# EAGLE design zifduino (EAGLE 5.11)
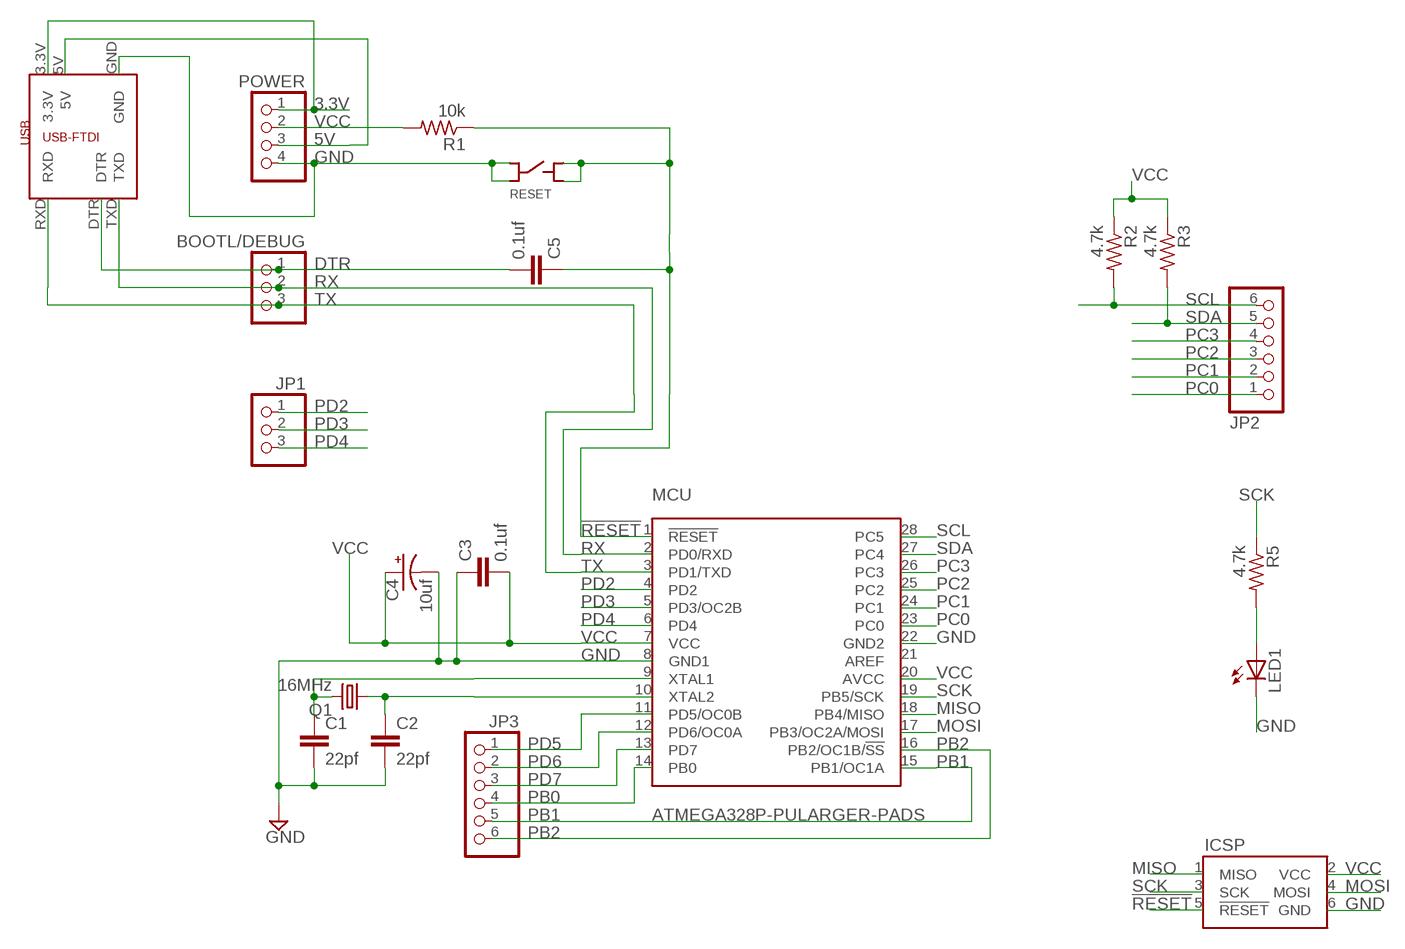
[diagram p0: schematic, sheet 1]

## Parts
BOOTL/DEBUG  PINHD-1X3  [1X03]
C1  22pf  C-EUC0805  [C0805]
C2  22pf  C-EUC0805  [C0805]
C3  0.1uf  C-EUC0805  [C0805]
C4  10uf  CPOL-USE2-4  [E2-4]
C5  0.1uf  C-EUC0805  [C0805]
ICSP  HEADER-AVR-PROG  [HEADER-AVR-PROG]
JP1  PINHD-1X3  [1X03]
JP2  PINHD-1X6  [1X06]
JP3  PINHD-1X6  [1X06]
LED1  LED5MM  [LED5MM]
MCU  ATMEGA328P-PULARGER-PADS  [DIL28-3-LARGER-PADS]
POWER  PINHD-1X4  [1X04]
Q1  16MHz  CRYSTALHC49U-V  [HC49U-V]
R1  10k  R-US_R0805  [R0805]
R2  4.7k  R-US_R1206  [R1206]
R3  4.7k  R-US_R1206  [R1206]
R5  4.7k  R-US_R1206  [R1206]
RESET  SFE-PUSHBUTTON-SWITCH  [SFE-PUSHBUTTON-SWITCH]
USB-FTDI  SFE-FTDI-BREAKOUT-MIN  [SFE-FTDI-BREAKOUT-MIN]

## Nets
3.3V: POWER.1 USB-FTDI.3.3V
5V: POWER.3 USB-FTDI.5V
!RESET: C5.1 ICSP.5(!RESET) MCU.1(!RESET) R1.1 RESET.O@1(O) RESET.O@2(O)
DTR: BOOTL/DEBUG.1 C5.2 USB-FTDI.DTR
GND: C1.2 C2.2 C3.1 C4.- ICSP.6(GND) LED1.K(C) MCU.8(GND1) MCU.22(GND2) POWER.4 RESET.C@1(C) RESET.C@2(C) USB-FTDI.GND
MISO: ICSP.1(MISO) MCU.18(PB4/MISO)
MOSI: ICSP.4(MOSI) MCU.17(PB3/OC2A/MOSI)
N$2: C2.1 MCU.10(XTAL2) Q1.1
N$3: C1.1 MCU.9(XTAL1) Q1.2
N$4: LED1.A R5.2
PB0: JP3.4 MCU.14(PB0)
PB1: JP3.5 MCU.15(PB1/OC1A)
PB2: JP3.6 MCU.16(PB2/OC1B/!SS)
PC0: JP2.1 MCU.23(PC0)
PC1: JP2.2 MCU.24(PC1)
PC2: JP2.3 MCU.25(PC2)
PC3: JP2.4 MCU.26(PC3)
PD2: JP1.1 MCU.4(PD2)
PD3: JP1.2 MCU.5(PD3/OC2B)
PD4: JP1.3 MCU.6(PD4)
PD5: JP3.1 MCU.11(PD5/OC0B)
PD6: JP3.2 MCU.12(PD6/OC0A)
PD7: JP3.3 MCU.13(PD7)
RX: BOOTL/DEBUG.2 MCU.2(PD0/RXD) USB-FTDI.TXD
SCK: ICSP.3(SCK) MCU.19(PB5/SCK) R5.1
SCL: JP2.6 MCU.28(PC5) R2.2
SDA: JP2.5 MCU.27(PC4) R3.2
TX: BOOTL/DEBUG.3 MCU.3(PD1/TXD) USB-FTDI.RXD
VCC: C3.2 C4.+ ICSP.2(VCC) MCU.7(VCC) MCU.20(AVCC) POWER.2 R1.2 R2.1 R3.1
Unconnected: MCU.21(AREF)

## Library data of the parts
BOOTL/DEBUG JP1 = pinhead:PINHD-1X3: PIN HEADER
C1-C3 C5 = rcl:C-EU: CAPACITOR, European symbol
C4 = rcl:CPOL-US: POLARIZED CAPACITOR, American symbol
ICSP = trl:HEADER-AVR-PROG
JP2 JP3 = pinhead:PINHD-1X6: PIN HEADER
LED1 = led:LED: LED
MCU = trl:ATMEGA328P-PU
POWER = pinhead:PINHD-1X4: PIN HEADER
Q1 = crystal:CRYSTAL: CRYSTAL; OC_FARNELL: 1666969; OC_NEWARK: unknown
R1-R3 R5 = resistor:R-US_: RESISTOR, American symbol
RESET = trl:SFE-PUSHBUTTON-SWITCH
USB-FTDI = trl:SFE-FTDI-BREAKOUT-MIN

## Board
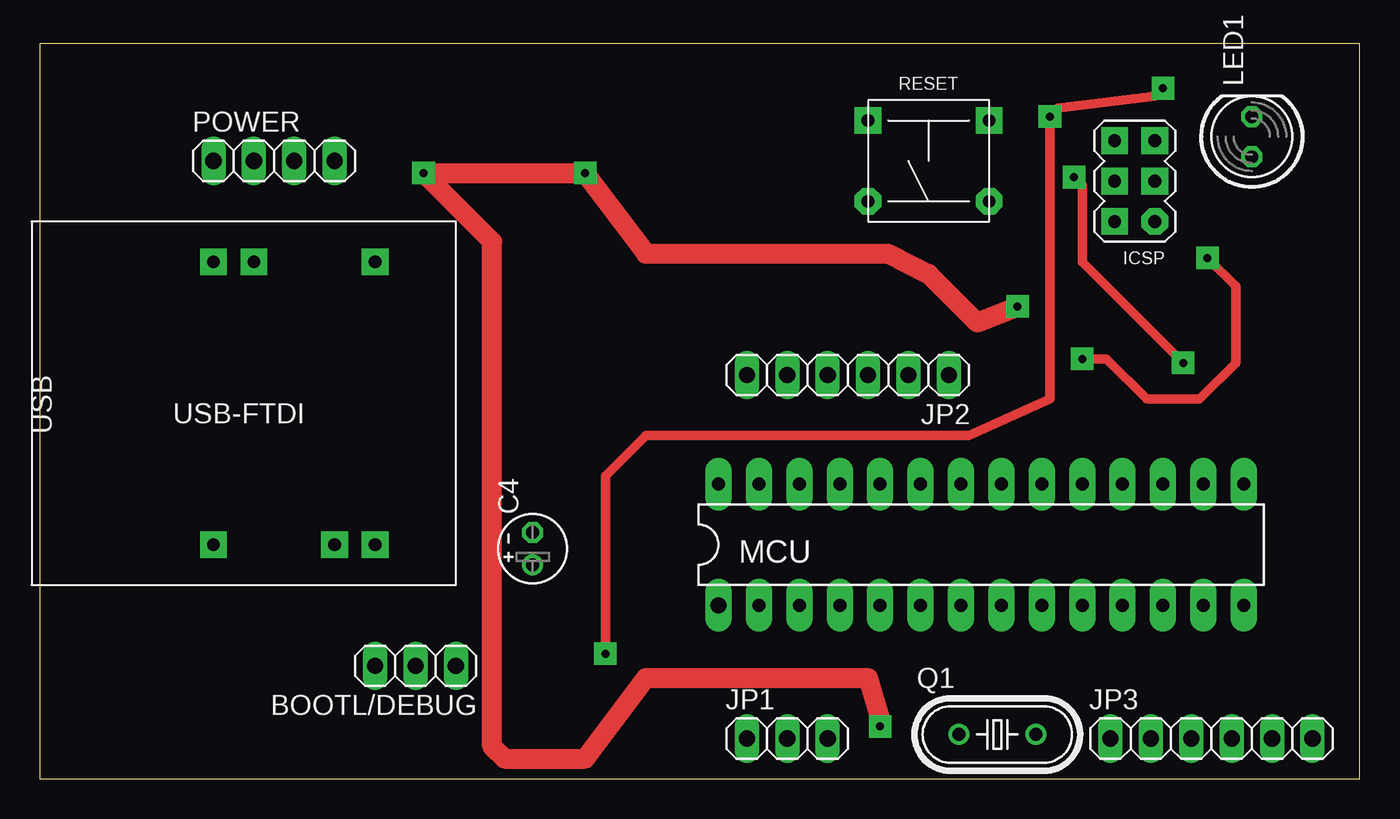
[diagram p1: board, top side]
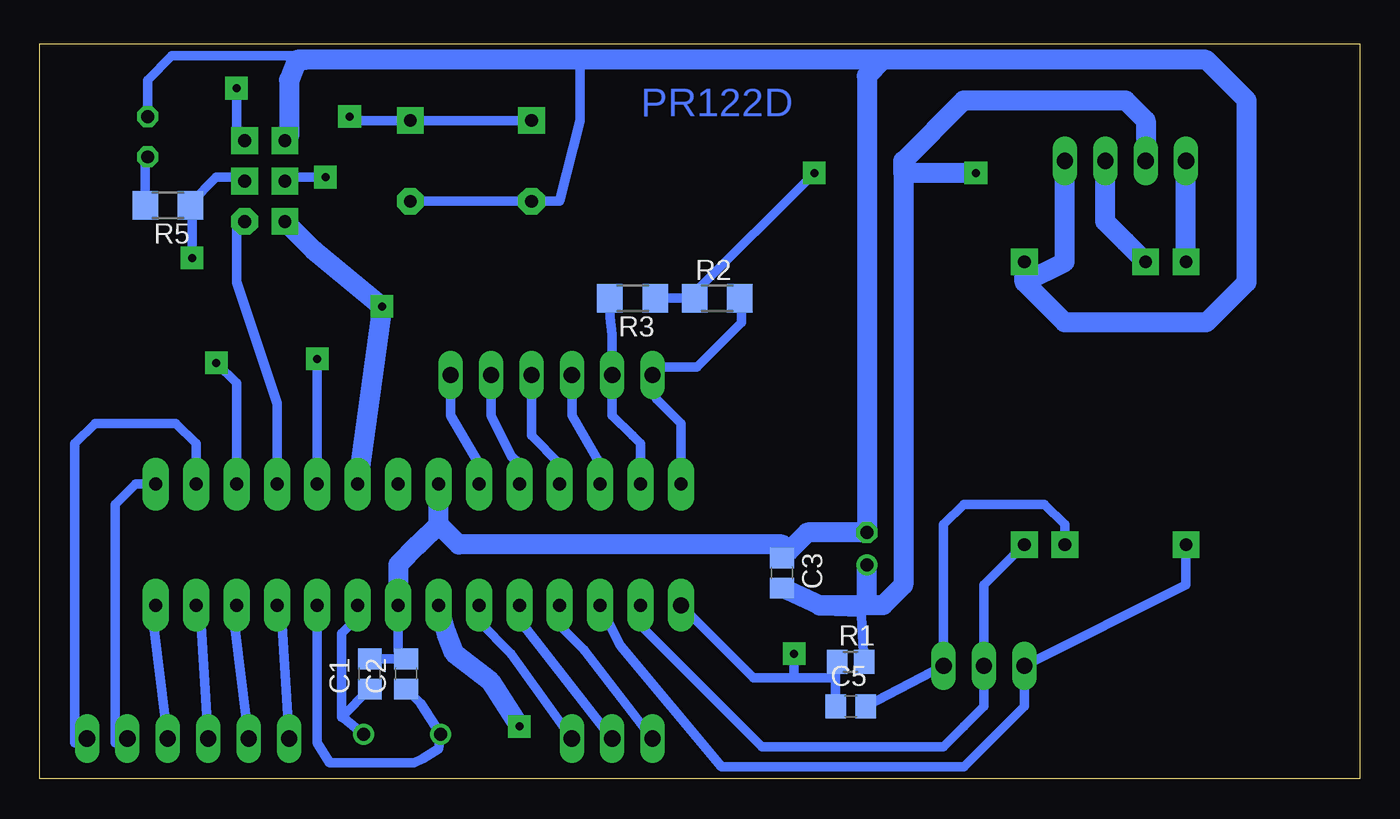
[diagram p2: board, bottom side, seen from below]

Size 82.98 x 46.22 mm. Coordinates in mm from the lower left corner, seen from the top.
Outline: 0,0 82.98,0 82.98,46.22 0,46.22 0,0
Copper layers (1*16): Top 0.035mm / dielectric 1.5mm / Bottom 0.035mm
Design rules "default *": minimum track width 10mil, minimum drill 19mil, track to track 8mil, track to pad 8mil, pad to pad 8mil, via to via 8mil, smd to smd 8mil, copper to edge 10mil, drill to drill 8mil, minimum pad ring 10mil, minimum via ring 8mil, stop-mask expansion 4mil, vias tented up to drill 0mil, thermal gap 10mil

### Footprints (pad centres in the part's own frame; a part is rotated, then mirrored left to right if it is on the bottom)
1X03 = drill 1.016 long: 1 -2.54,0; 2 0,0; 3 2.54,0
C0805 = smd 1.3 x 1.5: 1 -0.95,0; 2 0.95,0
E2-4 = drill 0.813 pad 1.27 round: + -1.016,0 | drill 0.813 pad 1.27 octagon: - 1.016,0
HEADER-AVR-PROG = drill 0.8 pad 1.676 octagon: 1 -2.54,-1.27 | drill 0.8 pad 1.676 square: 2 -2.54,1.27; 3 0,-1.27; 4 0,1.27; 5 2.54,-1.27; 6 2.54,1.27
1X06 = drill 1.016 long: 1 -6.35,0; 2 -3.81,0; 3 -1.27,0; 4 1.27,0; 5 3.81,0; 6 6.35,0
LED5MM = drill 0.813 octagon: A -1.27,0; K 1.27,0
DIL28-3-LARGER-PADS = drill 1 pad 1.676 long: 1 -16.51,-3.81 | drill 0.813 pad 1.676 long: 2 -13.97,-3.81; 3 -11.43,-3.81; 4 -8.89,-3.81; 5 -6.35,-3.81; 6 -3.81,-3.81; 7 -1.27,-3.81; 8 1.27,-3.81; 9 3.81,-3.81; 10 6.35,-3.81; 11 8.89,-3.81; 12 11.43,-3.81; 13 13.97,-3.81; 14 16.51,-3.81; 15 16.51,3.81; 16 13.97,3.81; 17 11.43,3.81; 18 8.89,3.81; 19 6.35,3.81; 20 3.81,3.81; 21 1.27,3.81; 22 -1.27,3.81; 23 -3.81,3.81; 24 -6.35,3.81; 25 -8.89,3.81; 26 -11.43,3.81; 27 -13.97,3.81; 28 -16.51,3.81
1X04 = drill 1.016 long: 1 -3.81,0; 2 -1.27,0; 3 1.27,0; 4 3.81,0
HC49U-V = drill 0.813 round: 1 -2.413,0; 2 2.413,0
R0805 = smd 1.3 x 1.5: 1 -0.85,0; 2 0.85,0
R1206 = smd 1.6 x 1.803: 1 -1.422,0; 2 1.422,0
SFE-PUSHBUTTON-SWITCH = drill 0.8 pad 1.676 octagon: C@1 -3.81,-2.54; C@2 3.81,-2.54 | drill 0.8 pad 1.676 square: O@1 -3.81,2.54; O@2 3.81,2.54
SFE-FTDI-BREAKOUT-MIN = drill 0.8 pad 1.676 square: 3.3V -2.54,8.89; 5V 0,8.89; DTR 5.08,-8.89; GND 7.62,8.89; RXD -2.54,-8.89; TXD 7.62,-8.89

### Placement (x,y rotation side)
BOOTL/DEBUG  23.62,7.11 180 top
C1  62.23,6.6 90 bottom
C2  59.94,6.6 90 bottom
C3  36.32,12.95 270 bottom
C4  30.99,14.48 90 top
C5  32,4.57 0 bottom
ICSP  68.83,37.59 90 top
JP1  46.99,2.54 0 top
JP2  50.8,25.4 180 top
JP3  73.66,2.54 0 top
LED1  76.2,40.39 90 top
MCU  59.18,14.73 0 top
POWER  14.73,38.86 0 top
Q1  60.2,2.79 0 top
R1  32,7.37 0 bottom
R2  40.39,30.23 0 bottom
R3  45.72,30.23 180 bottom
R5  74.93,36.07 180 bottom
RESET  55.88,38.86 0 top
USB-FTDI  13.46,23.62 0 top

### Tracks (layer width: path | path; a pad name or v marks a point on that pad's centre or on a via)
3.3V
  Bottom 1.27: USB-FTDI.3.3V POWER.1
5V
  Bottom 1.27: USB-FTDI.5V 14.73,33.78 16,35.05 POWER.3
!RESET  (via drill 0.5 pad 1.42)
  Top 0.61: v70.61,43.43 70.1,42.93 64.01,42.16 v63.5,41.66 63.5,40.64 63.5,33.27 63.5,31.5 63.5,23.88 58.42,21.59 38.1,21.59 35.56,19.05 v35.56,7.87
  Bottom 0.61: RESET.O@1 RESET.O@2 63.5,41.4 v63.5,41.66 | C5.1 32.95,6.35 | 32.95,6.35 32.95,7.27 R1.1 | v70.61,43.43 70.61,40.64 ICSP.5 | 38.1,6.35 MCU.1 38.1,6.35 | 32.95,6.35 35.56,6.35 | 35.56,6.35 38.1,6.35 | 38.1,6.35 35.56,6.35 | 35.56,6.35 v35.56,7.87
DTR
  Bottom 0.61: C5.2 BOOTL/DEBUG.1 26.16,16 24.89,17.27 19.81,17.27 18.54,16 USB-FTDI.DTR
GND
  Bottom 0.61: RESET.C@2 RESET.C@1 52.83,36.32 50.29,36.32 49.02,41.4 49.02,45.21 | MCU.8 60.45,8.06 C2.2 C1.2 | LED1.K 76.2,43.94 74.68,45.47 66.55,45.47 66.29,45.21
  Bottom 1.27: 21.08,31.24 USB-FTDI.GND 21.08,31.24 | 21.08,31.24 18.54,32.51 POWER.4 | 21.08,31.24 18.54,28.7 9.65,28.7 7.11,31.24 7.11,42.67 9.65,45.21 29.97,45.21 | 29.97,45.21 49.02,45.21 66.29,45.21 66.8,45.21 67.31,43.94 67.31,40.39 ICSP.6 | MCU.8 60.45,13.46 59.18,14.73 57.91,16 | 57.91,16 MCU.22 57.91,16 | 29.97,45.21 30.99,44.2 C4.- 34.73,15.49 35.91,14.32 | 35.91,14.32 C3.1 | 57.91,16 56.64,14.73 36.32,14.73 35.91,14.32
MISO
  Bottom 0.61: MCU.18 68.07,23.62 70.61,31.24 70.61,34.54 ICSP.1
MOSI  (via drill 0.5 pad 1.42)
  Top 0.61: v71.88,26.16 65.53,32.51 65.53,37.34 v65.02,37.85
  Bottom 0.61: MCU.17 70.61,24.89 v71.88,26.16 | v65.02,37.85 67.31,37.85 ICSP.4
N$2
  Bottom 0.61: MCU.10 65.53,2.29 64.77,1.02 59.44,1.02 58.93,1.27 57.91,1.91 Q1.1 59.05,4.76 C2.1
N$3
  Bottom 0.61: MCU.9 62.99,10.16 64.01,9.14 64.01,3.94 | Q1.2 64.01,3.94 | 64.01,3.94 64.01,3.88 C1.1
N$4
  Bottom 0.61: R5.2 76.35,38.96 LED1.A
PB0
  Bottom 0.61: JP3.4 75.95,10.67 MCU.14
PB1
  Bottom 0.61: MCU.15 76.96,18.54 78.23,17.27 78.23,2.29 JP3.5
PB2
  Bottom 0.61: MCU.16 73.15,21.08 74.42,22.35 79.5,22.35 80.77,21.08 80.77,2.29 JP3.6
PC0
  Bottom 0.61: MCU.23 55.37,19.81 57.15,22.86 57.15,24.38 JP2.1
PC1
  Bottom 0.61: MCU.24 52.83,19.81 53.34,20.32 54.61,22.86 54.61,24.38 JP2.2
PC2
  Bottom 0.61: MCU.25 50.29,19.81 52.07,21.59 52.07,22.86 52.07,24.38 JP2.3
PC3
  Bottom 0.61: MCU.26 47.75,19.81 49.53,22.86 49.53,24.38 JP2.4
PD2
  Bottom 0.61: JP1.1 48.77,8.13 50.29,9.65 MCU.4
PD3
  Bottom 0.61: JP1.2 52.58,9.65 52.83,9.91 MCU.5
PD4
  Bottom 0.61: JP1.3 53.34,7.87 55.37,9.91 MCU.6
PD5
  Bottom 0.61: JP3.1 67.82,10.67 MCU.11
PD6
  Bottom 0.61: JP3.2 70.87,10.67 MCU.12
PD7
  Bottom 0.61: JP3.3 72.9,10.67 MCU.13
RX
  Bottom 0.61: USB-FTDI.TXD 23.62,12.19 BOOTL/DEBUG.2 23.62,4.57 24.89,3.3 26.16,2.03 37.59,2.03 45.21,9.65 MCU.2
SCK  (via drill 0.5 pad 1.42)
  Top 0.61: v65.53,26.42 67.06,26.42 69.6,23.88 72.9,23.88 75.18,26.16 75.18,30.99 v73.41,32.77
  Bottom 0.61: ICSP.3 70.36,37.85 71.88,37.85 73.51,36.22 R5.1 73.41,35.97 v73.41,32.77 | MCU.19 v65.53,26.42
SCL
  Bottom 0.61: R2.2 38.86,30.12 38.86,29.97 38.86,28.7 41.66,25.91 44.7,25.91 44.2,23.88 | 44.2,23.88 JP2.6 | MCU.28 42.67,22.35 44.2,23.88
SDA
  Bottom 0.61: R3.2 47.14,29.06 46.99,27.94 46.99,25.65 | 46.99,25.65 46.99,24.89 JP2.5 46.99,25.65 | MCU.27 45.21,21.08 45.72,21.59 46.99,22.86 46.99,24.13 46.99,25.65
TX
  Bottom 0.61: USB-FTDI.RXD 10.92,12.19 BOOTL/DEBUG.3 21.08,4.57 24.89,0.76 40.13,0.76 46.48,8.38 MCU.3
VCC  (via drill 0.5 pad 1.42)
  Top 1.27: v61.47,29.72 58.93,28.7 55.88,31.75 53.34,33.02 38.1,33.02 v34.29,38.1 v24.13,38.1 28.45,33.78 28.45,2.03 29.21,1.27 34.29,1.27 38.1,6.35 52.07,6.35 52.83,3.81 v52.83,3.3
  Bottom 0.61: 31.36,10.83 R1.2 | R3.1 R2.1 41.81,30.58 v34.29,38.1
  Bottom 1.27: C3.2 33.95,10.9 31.36,10.83 33.81,10.92 31.24,10.92 | POWER.2 13.46,41.4 14.73,42.67 24.89,42.67 28.7,38.86 28.7,38.1 | 28.7,38.1 28.7,12.19 29.97,10.92 31.24,10.92 | C4.+ 30.99,11.18 31.24,10.92 | MCU.20 v61.47,29.72 65.79,33.27 ICSP.2 | v24.13,38.1 28.7,38.1 | MCU.7 57.4,9.14 56.9,7.87 54.61,6.1 v52.83,3.3

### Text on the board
Bottom: PR122D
